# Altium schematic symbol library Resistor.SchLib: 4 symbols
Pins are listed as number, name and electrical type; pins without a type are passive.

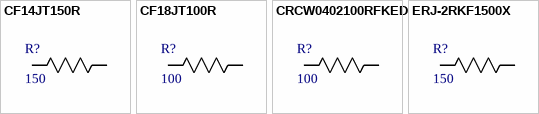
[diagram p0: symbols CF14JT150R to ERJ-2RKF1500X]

## CF14JT150R
designator R?, comment 150
150 Ohms ±5% 0.25W, 1/4W Through Hole Resistor Axial Carbon Film; Manufacturer_Name: Stackpole International; Manufacturer_Part_Number: CF14JT150R
footprint CF14JT150R (150 Ohms ±5% 0.25W, 1/4W Through Hole Resistor Axial Carbon Film)
pins: 1, 2

## CF18JT100R
designator R?, comment 100
100 Ohms ±5% 0.125W, 1/8W Through Hole Resistor Axial Carbon Film; Manufacturer_Name: Stackpole International; Manufacturer_Part_Number: CF18JT100R
footprint CF18JT100R (100 Ohms ±5% 0.125W, 1/8W Through Hole Resistor Axial Carbon Film)
pins: 1, 2

## CRCW0402100RFKED
designator R?, comment 100
100 Ohms ±1% 0.063W, 1/16W Chip Resistor 0402 (1005 Metric) Automotive AEC-Q200 Thick Film; Manufacturer_Name: Vishay; Manufacturer_Part_Number: CRCW0402100RFKED
footprint CRCW0402100RFKED (100 Ohms ±1% 0.063W, 1/16W Chip Resistor 0402 (1005 Metric) Automotive AEC-Q200 Thick Film)
pins: 1, 2

## ERJ-2RKF1500X
designator R?, comment 150
150 Ohms ±1% 0.1W, 1/10W Chip Resistor 0402 (1005 Metric) Automotive AEC-Q200 Thick Filmn; Manufacturer_Name: Panasonic; Manufacturer_Part_Number: ERJ-2RKF1500X
footprint ERJ-2RKF1500X (150 Ohms ±1% 0.1W, 1/10W Chip Resistor 0402 (1005 Metric) Automotive AEC-Q200 Thick Film)
pins: 1, 2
